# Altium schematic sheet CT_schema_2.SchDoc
size 276 x 169 mm
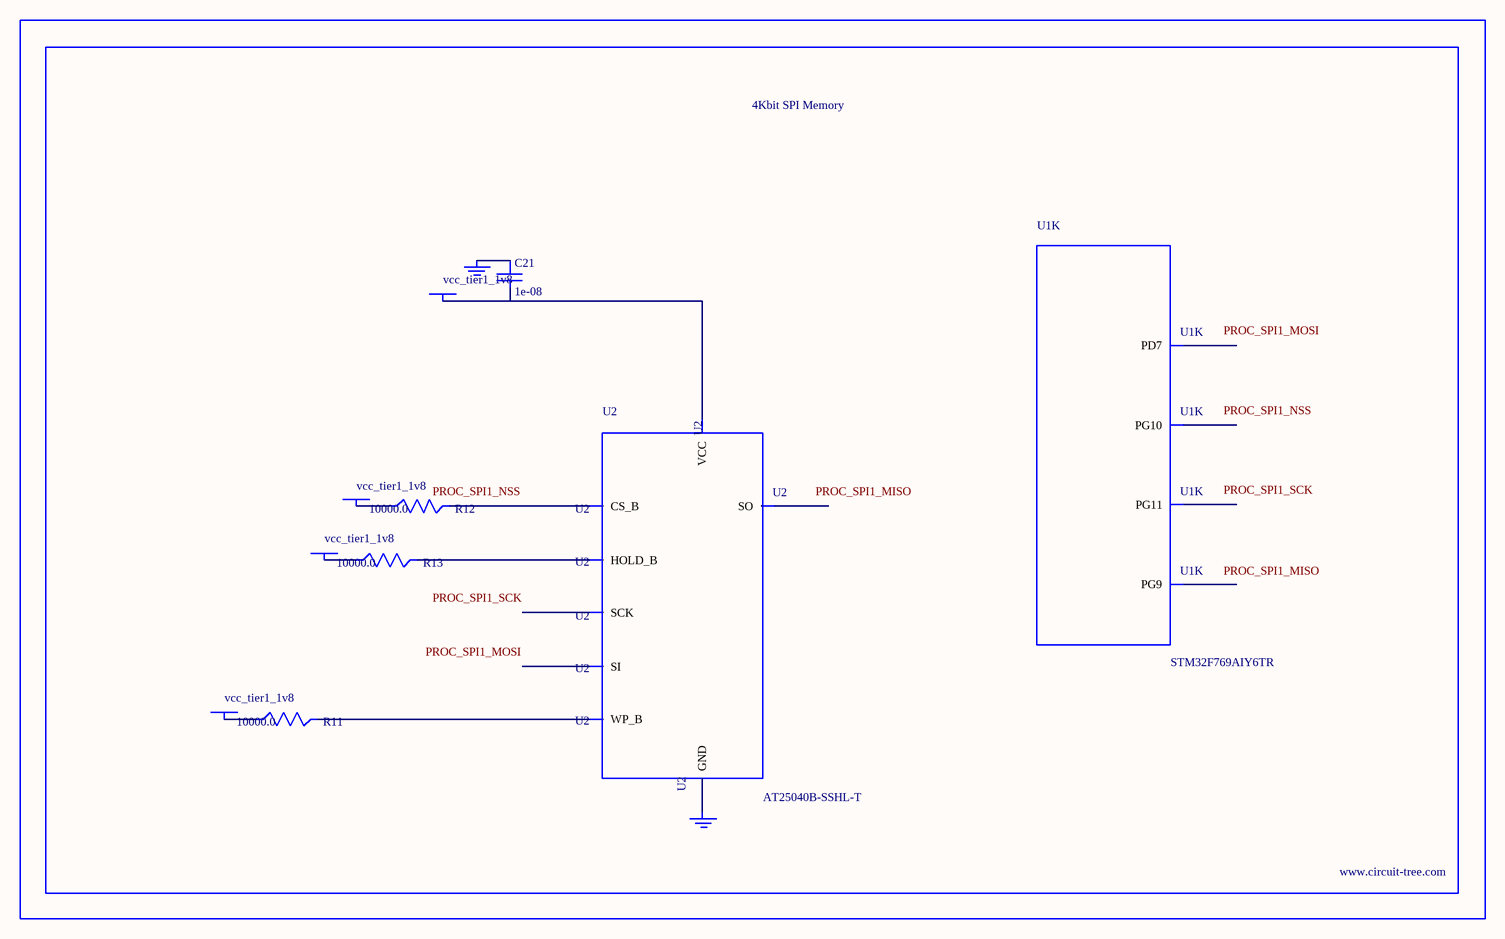
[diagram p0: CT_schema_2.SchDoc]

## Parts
BORDER1  (no value)
C21  1e-08  [C0402]
GND_INSTANCE_1_0  (no value)
GND_INSTANCE_1_1  (no value)
POWER_INSTANCE_1_0  vcc_tier1_1v8
POWER_INSTANCE_1_1  vcc_tier1_1v8
POWER_INSTANCE_1_2  vcc_tier1_1v8
POWER_INSTANCE_1_3  vcc_tier1_1v8
R11  10000.0  [R0603]
R12  10000.0  [R0603]
R13  10000.0  [R0603]
U1  STM32F769AIY6TR  [WLCSP180]  (part K of 15)
U2  AT25040B-SSHL-T  [SOIC-8]

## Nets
NetC21_1: C21.1 GND_INSTANCE_1_0.0(GND)
NetC21_2: C21.2 POWER_INSTANCE_1_3.0(PWR) U2.8(VCC)
NetGND_INSTANCE_1_1_0: GND_INSTANCE_1_1.0(GND) U2.4(GND)
NetPOWER_INSTANCE_1_0_0: POWER_INSTANCE_1_0.0(PWR) R12.1
NetPOWER_INSTANCE_1_1_0: POWER_INSTANCE_1_1.0(PWR) R11.1
NetPOWER_INSTANCE_1_2_0: POWER_INSTANCE_1_2.0(PWR) R13.1
NetR11_2: R11.2 U2.3(WP_B)
NetR12_2: R12.2 U2.1(CS_B)
NetR13_2: R13.2 U2.7(HOLD_B)

Not connected (* = marked no-connect by the designer): U1 A7(PG10) B7(PG11) C6(PG9) E7(PD7); U2 2(SO) 5(SI) 6(SCK)

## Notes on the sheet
- Labels drawn without touching a wire or pin: PROC_SPI1_MISO, PROC_SPI1_MOSI, PROC_SPI1_NSS, PROC_SPI1_SCK

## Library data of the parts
BORDER1 = BORDER_PAGE1
C21 = C0402C103K3RAC
GND_INSTANCE_1_0 GND_INSTANCE_1_1 = GND
POWER_INSTANCE_1_0-POWER_INSTANCE_1_3 = PWR
R11-R13 = RC0603JR-0710KL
